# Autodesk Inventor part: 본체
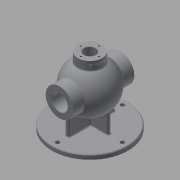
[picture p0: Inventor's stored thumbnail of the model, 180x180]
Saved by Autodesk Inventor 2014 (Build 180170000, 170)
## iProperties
Created: 2020-08
Part Number: 본체
Material: Generic
Document SubType Name: Modeling
Designer: kh
Density: 1 g/cm^3
Appearance: Default
Author: kh
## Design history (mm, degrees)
sketch "Sketch1"
  geometry: C1 r 85 at (0, 0); 1 further point
  constraints: 1 centre point, 1 coincident
  dimensions: "d0" = 170 diameter of C1
extrude "Extrusion1" new body sketch "Sketch1" distance "d1" = 10; taper "d2" = 0 deg
sketch "Sketch2"
  geometry: L1 (85, 10)-(85, 0) reference; L2 (85, 0)-(-85, 0) reference; L3 (-85, 0)-(-85, 10) reference; L4 (-85, 10)-(85, 10) reference; L5 (85, 10)-(85, 0) reference; L6 (85, 0)-(-85, 0) reference; L7 (-85, 0)-(-85, 10) reference; L8 (-85, 10)-(85, 10) reference; L9 (0, 0)-(0, 85); L10 (-68, 85)-(68, 85); L11 (42.988, 116)-(68, 116); L12 (0, 85)-(0, 138); L13 (68, 116)-(68, 102.5); L14 (68, 102.5)-(39.278, 102.5); L15 (-42.988, 116)-(-68, 116); L16 (-68, 116)-(-68, 102.5); L17 (-68, 102.5)-(-39.278, 102.5); A1 r 53 centre (0, 85) between (42.988, 116) and (0, 138); A2 r 43 centre (0, 85) between (39.278, 102.5) and (0, 128); A3 r 43 centre (0, 85) between (0, 128) and (-39.278, 102.5); A4 r 53 centre (0, 85) between (0, 138) and (-42.988, 116)
  constraints: 18 end point, 8 point on circle, 4 centre point, 4 perpendicular, 4 symmetric about line, 3 coincident, 2 parallel, 1 midpoint, 1 point on line, 1 vertical alignment, 2 other
  dimensions: "d3" = 85 distance of L9.end L9.start; "d4" = 53 radius of A1; "d5" = 43 radius of A2; "d7" = 62 diameter of L11.end L10; "d8" = 35 diameter of L13.end L10; "d9" = 136 distance of L10.start L10.end
revolve "Revolution1" sketch "Sketch2" stored, may be unused: angle "d15" = 90 deg
workplane "Work Plane1"
sketch "Sketch4"
  geometry: L1 (31, -42.988)-(-31, -42.988) reference; L2 (31, 42.988)-(-31, 42.988) reference; C1 r 27 at (0, 0); A1 r 53 centre (0, 0) between (-31, 42.988) and (31, 42.988) reference; 1 further point
  constraints: 1 centre point, 1 coincident
  dimensions: "d25" = 54 diameter of C1
extrude "Extrusion2" join sketch "Sketch4" stored distance "d26" = 10; taper "d27" = 0 deg
sketch "Sketch5"
  geometry: C1 r 27 at (0, 0) reference; C2 r 13 at (0, 0); 1 further point
  constraints: 1 centre point, 1 coincident
  dimensions: "d28" = 26 diameter of C2
extrude "Extrusion3" cut sketch "Sketch5" stored distance "d29" = 10; taper "d30" = 0 deg
sketch "Sketch6"
  geometry: L1 (0, 27)-(0, -27); L2 (27, 0)-(-27, 0); C1 r 13 at (0, 0) reference; A1 r 27 centre (0, 0) between (0, 27) and (0, -27) reference; A2 r 20 centre (0, 0) between (20, 0) and (0, 20); 6 further points
  constraints: 7 point on circle, 5 midpoint, 4 end point, 4 point on line, 1 centre point, 1 coincident, 1 horizontal, 1 horizontal alignment, 1 vertical, 1 other
  dimensions: "d31" = 40 diameter of A2
hole "Hole1" sketch "Sketch6" at (20, 0), (0, 20), (-20, 0), (0, -20) diameter "d32" = 3.242; stored, may be unused: countersink angle "d36" = 90 deg, drill point angle "d38" = 118 deg; dims "d33" = 12, "d34" = 4, "d35" = 2, "d37" = 15
sketch "Sketch7"
  geometry: L1 (-51, -85)-(-51, -75) reference; L2 (-51, -75)-(51, -75) reference; L3 (51, -75)-(51, -85) reference; L4 (51, -85)-(-51, -85) reference; L5 (0, 31)-(0, -31); L6 (-31, 0)-(31, 0); C1 r 17.5 at (0, 0) reference; A1 r 31 centre (0, 0) between (0, 31) and (0, -31) reference; A2 r 24 centre (0, 0) between (-24, 0) and (0, 24); 5 further points
  constraints: 8 point on circle, 4 end point, 4 midpoint, 4 point on line, 2 perpendicular, 1 centre point, 1 coincident
  dimensions: "d39" = 48 diameter of A2
hole "Hole2" sketch "Sketch7" at (-24, 0), (0, 24), (24, 0), (0, -24) diameter "d40" = 3.242; stored, may be unused: countersink angle "d44" = 90 deg, drill point angle "d46" = 118 deg; dims "d41" = 12, "d42" = 4, "d43" = 2, "d45" = 15
mirror "Mirror1"
sketch "Sketch8"
  geometry: L1 (-4, 52)-(4, 52); L2 (4, 52)-(4, -52); L3 (4, -52)-(-4, -52); L4 (-4, -52)-(-4, 52); L5 (-4, 52)-(4, -52); L6 (4, 52)-(-4, -52); L7 (-43, 4)-(43, 4); L8 (43, 4)-(43, -4); L9 (43, -4)-(-43, -4); L10 (-43, -4)-(-43, 4); L11 (-43, 4)-(43, -4); L12 (43, 4)-(-43, -4); C1 r 85 at (0, 0) reference
  constraints: 24 end point, 4 midpoint, 4 parallel, 2 horizontal, 2 perpendicular
  dimensions: "d49" = 8 distance of L2.end L3.end; "d50" = 104 distance of L1.end L2.end; "d51" = 86 distance of L8.end L9.end; "d52" = 8 distance of L7.end L8.end
extrude "Extrusion4" join sketch "Sketch8" stored distance "d53" = 10; taper "d54" = 0 deg
sketch "Sketch9"
  geometry: L1 (-43, 4)-(-4, 4) reference; L2 (-4, 4)-(-4, 52) reference; L3 (-4, 52)-(4, 52) reference; L4 (4, 52)-(4, 4) reference; L5 (4, 4)-(43, 4) reference; L6 (43, 4)-(43, -4) reference; L7 (43, -4)-(4, -4) reference; L8 (4, -4)-(4, -52) reference; L9 (4, -52)-(-4, -52) reference; L10 (-4, -52)-(-4, -4) reference; L11 (-4, -4)-(-43, -4) reference; L12 (-43, -4)-(-43, 4) reference; L13 (0, 85)-(0, -85); L14 (85, 0)-(-85, 0); C1 r 4.5 at (0, 72.5); C2 r 4.5 at (72.5, 0); C3 r 4.5 at (0, -72.5); C4 r 4.5 at (-72.5, 0); A1 r 85 centre (0, 0) between (0, 85) and (0, -85) reference; A2 r 72.5 centre (0, 0) between (0, 72.5) and (72.5, 0); 2 further points
  constraints: 8 point on circle, 5 centre point, 4 end point, 4 point on line, 3 equal radius, 3 midpoint, 2 parallel, 1 coincident
  dimensions: "d55" = 145 diameter of A2; "d56" = 9 diameter of C1
extrude "Extrusion5" cut sketch "Sketch9" stored distance "d57" = 10; taper "d58" = 0 deg
workplane "Work Plane2"
sketch "Sketch10"
  geometry: L1 (-59.206, -31.786)-(59.206, -31.786); L2 (59.206, -31.786)-(59.206, 13.786); L3 (59.206, 13.786)-(-59.206, 13.786); L4 (-59.206, 13.786)-(-59.206, -31.786); L5 (-59.206, -31.786)-(59.206, 13.786); L6 (59.206, -31.786)-(-59.206, 13.786); L7 (-27, 0)-(-27, -19.393) reference; L8 (-27, 0)-(27, 0) reference; L9 (27, 0)-(27, -19.393) reference; L10 (-27, -19.393)-(27, -19.393) reference; 2 further points
  constraints: 4 end point, 1 midpoint, 2 other
  dimensions: "d59" = 9 distance from line of L8 point (0, -9); "d60" = 27 distance from line of L7 point (0, -9)
emboss "Emboss1" sketch "Sketch10" dims "d61" = 0.5, "d62" = 0
fillet "Fillet1" dims "d63" = 3
fillet "Fillet2" dims "d64" = 3
fillet "Fillet3" dims "d65" = 3
fillet "Fillet4" dims "d66" = 3
chamfer "Chamfer1" distance "d67" = 1; stored, may be unused: second distance "d68" = 2, angle "d69" = 45 deg
sketch "Sketch11"
  geometry: L1 (85, 7)-(85, 0) reference; L2 (85, 0)-(77, 0) reference; L3 (77, 0)-(77, 10) reference; L4 (77, 10)-(82, 10) reference; L5 (-82, 10)-(-77, 10) reference; L6 (-77, 10)-(-77, 0) reference; L7 (-77, 0)-(-85, 0) reference; L8 (-85, 0)-(-85, 7) reference; L9 (-52.026, 61)-(-53, 62.621) reference; L10 (-53, 62.621)-(-68, 62.621) reference; L11 (-68, 62.621)-(-68, 66.5) reference; L12 (-67, 67.5)-(-39.278, 67.5) reference; L13 (39.278, 67.5)-(67, 67.5) reference; L14 (68, 66.5)-(68, 62.621) reference; L15 (68, 62.621)-(53, 62.621) reference; L16 (53, 62.621)-(52.026, 61) reference; L17 (52.026, 61)-(53, 59.379) reference; L18 (53, 59.379)-(68, 59.379) reference; L19 (68, 59.379)-(68, 54) reference; L20 (68, 54)-(55, 54) reference; L21 (52, 51)-(52, 13) reference; L22 (55, 10)-(68, 10) reference; L23 (68, 10)-(68, 0) reference; L24 (68, 0)-(-68, 0) reference; L25 (-68, 0)-(-68, 10) reference; L26 (-68, 10)-(-55, 10) reference; L27 (-52, 13)-(-52, 51) reference; L28 (-55, 54)-(-68, 54) reference; L29 (-68, 54)-(-68, 59.379) reference; L30 (-68, 59.379)-(-53, 59.379) reference; L31 (-53, 59.379)-(-52.026, 61) reference; L32 (20, 134.026)-(21.621, 135) reference; L33 (21.621, 135)-(21.621, 150) reference; L34 (21.621, 150)-(27, 150) reference; L35 (27, 150)-(27, 132.286) reference; L36 (44.497, 116)-(68, 116) reference; L37 (68, 116)-(68, 110.621) reference; L38 (68, 110.621)-(53, 110.621) reference; L39 (53, 110.621)-(52.026, 109) reference; L40 (52.026, 109)-(53, 107.379) reference; L41 (53, 107.379)-(68, 107.379) reference; L42 (68, 107.379)-(68, 103.5) reference; L43 (67, 102.5)-(39.278, 102.5) reference; L44 (13, 125.988)-(13, 149) reference; L45 (13, 149)-(14, 150) reference; L46 (14, 150)-(18.379, 150) reference; L47 (18.379, 150)-(18.379, 135) reference; L48 (18.379, 135)-(20, 134.026) reference; L49 (-20, 134.026)-(-18.379, 135) reference; L50 (-18.379, 135)-(-18.379, 150) reference; L51 (-18.379, 150)-(-14, 150) reference; L52 (-14, 150)-(-13, 149) reference; L53 (-13, 149)-(-13, 125.988) reference; L54 (-39.278, 102.5)-(-67, 102.5) reference; L55 (-68, 103.5)-(-68, 107.379) reference; L56 (-68, 107.379)-(-53, 107.379) reference; L57 (-53, 107.379)-(-52.026, 109) reference; L58 (-52.026, 109)-(-53, 110.621) reference; L59 (-53, 110.621)-(-68, 110.621) reference; L60 (-68, 110.621)-(-68, 116) reference; L61 (-68, 116)-(-44.497, 116) reference; L62 (-27, 132.286)-(-27, 150) reference; L63 (-27, 150)-(-21.621, 150) reference; L64 (-21.621, 150)-(-21.621, 135) reference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; A1 r 3 centre (82, 7) between (85, 7) and (82, 10) reference; A2 r 3 centre (-82, 7) between (-82, 10) and (-85, 7) reference; A3 r 43 centre (0, 85) between (-39.278, 67.5) and (39.278, 67.5) reference; A4 r 3 centre (55, 51) between (55, 54) and (52, 51) reference; A5 r 3 centre (55, 13) between (52, 13) and (55, 10) reference; A6 r 3 centre (-55, 13) between (-55, 10) and (-52, 13) reference; A7 r 3 centre (-55, 51) between (-52, 51) and (-55, 54) reference; A8 r 3 centre (30, 132.286) between (27, 132.286) and (28.393, 129.753) reference; A9 r 53 centre (0, 85) between (42.113, 117.179) and (28.393, 129.753) reference; A10 r 3 centre (44.497, 119) between (42.113, 117.179) and (44.497, 116) reference; A11 r 43 centre (0, 85) between (39.278, 102.5) and (13, 125.988) reference; A12 r 43 centre (0, 85) between (-13, 125.988) and (-39.278, 102.5) reference; A13 r 3 centre (-44.497, 119) between (-44.497, 116) and (-42.113, 117.179) reference; A14 r 53 centre (0, 85) between (-28.393, 129.753) and (-42.113, 117.179) reference; A15 r 3 centre (-30, 132.286) between (-28.393, 129.753) and (-27, 132.286) reference; 1 further point
  constraints: 8 end point, 3 perpendicular, 2 midpoint, 2 point on line
  dimensions: "d72" = 16 distance between parallel lines of L66 L71; "d73" = 1.75 distance of L69.end L70.end; "d74" = 37 diameter of L69.end L68
revolve "Revolution3" sketch "Sketch11" stored, may be unused: angle "d75" = 90 deg
body "Solid1"
node "Projected Loop1"
node "Project Cut Edges1"
node "Project Cut Edges2"
node "Project Cut Edges4"
node "Project Cut Edges5"
node "Project Cut Edges6"
node "Project Cut Edges7"
node "Project Cut Edges8"
node "Project Cut Edges9"
